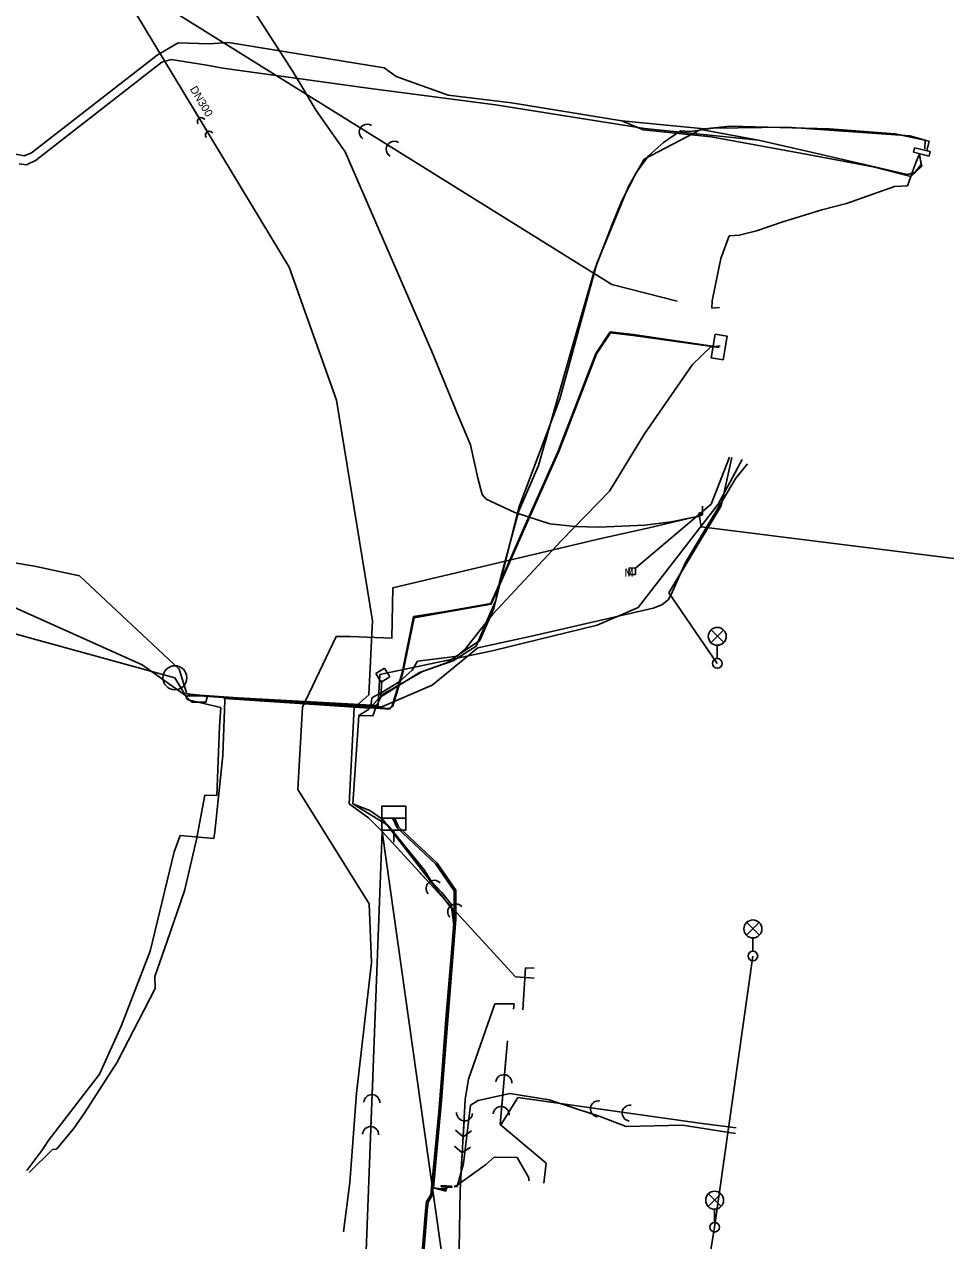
# Model space of a CAD drawing. Extents: x -880762 to -879575, y -1023083 to -1021277.
# Drawn here: x -880277.4 to -880162.3, y -1022636.5 to -1022484.5 of the extents above; entities that cross this region are included whole.
import ezdxf

# ---------------------------------------------------------------- set-up
doc = ezdxf.new("R2010")
doc.units = 0
for name, color, linetype in [('CETIN', 7, 'Continuous'), ('el_NN-dům_hrázného', 7, 'Continuous'), ('elektro skříň', 7, 'Continuous'), ('kanalizace trasa', 7, 'Continuous'), ('vedeni NN VN', 7, 'Continuous'), ('vedení sdělovací', 7, 'Continuous'), ('VODOVOD', 7, 'Continuous'), ('znaky inž sítí ostatní', 7, 'Continuous'), ('šoupe vodovod', 7, 'Continuous')]:
    doc.layers.add(name, color=color, linetype=linetype)

msp = doc.modelspace()

# ---------------------------------------------------------------- linework, layer by layer
at = {"layer": 'CETIN'}
for points in [[(-880193.98, -1022546.12), (-880196.64, -1022546.65), (-880199.92, -1022547.08), (-880205.66, -1022547.32), (-880208.59, -1022547.23), (-880211.79, -1022546.9), (-880216.17, -1022545.48), (-880219.74, -1022543.82), (-880220.26, -1022543.26), (-880220.79, -1022541.22), (-880221.68, -1022537.04), (-880223.2, -1022533.48), (-880226.53, -1022525.39), (-880237.36, -1022500.45), (-880240.99, -1022495.28), (-880243.91, -1022490.39), (-880249.48, -1022481.75)], [(-880192.72, -1022544.68), (-880192.72, -1022545.77)], [(-880192.72, -1022544.68), (-880192.72, -1022545.77)], [(-880193.98, -1022546.12), (-880199.21, -1022547.35), (-880205.76, -1022548.81), (-880231.39, -1022554.88), (-880231.51, -1022561.2), (-880236.72, -1022560.99), (-880238.48, -1022560.97), (-880242.7, -1022569.82), (-880243.26, -1022580.08), (-880234.35, -1022594.36), (-880234.08, -1022601.7), (-880235.96, -1022618.03), (-880236.79, -1022629.2), (-880237.56, -1022635.34)], [(-880192.72, -1022545.77), (-880193.29, -1022545.98), (-880193.98, -1022546.12)], [(-880193.19, -1022545.51), (-880192.72, -1022545.77)], [(-880193.19, -1022545.51), (-880192.87, -1022547.3), (-880158.34, -1022551.61), (-880115.31, -1022557.06), (-880085.69, -1022559.86), (-880050.13, -1022567.44), (-880017.98, -1022579.31), (-879984.34, -1022593.8), (-879953.77, -1022606.48), (-879894, -1022631.85), (-879832.89, -1022657.98), (-879784.6, -1022689.61), (-879745.83, -1022713), (-879719.83, -1022738.56), (-879689.51, -1022723.72), (-879660.2, -1022700.45), (-879600.68, -1022686.65), (-879574.8, -1022673.27)]]:
    msp.add_lwpolyline(points, dxfattribs=at)
at = {"layer": 'el_NN-dům_hrázného'}
msp.add_line((-880232.77, -1022566.49), (-880232.92, -1022568.52), dxfattribs=at)
for points in [[(-880164.93, -1022500.07), (-880164.9, -1022498.98), (-880166.82, -1022498.43), (-880182.19, -1022497.35), (-880191.37, -1022497.47), (-880194.24, -1022497.88), (-880195.47, -1022497.82), (-880197.57, -1022499.29), (-880199.48, -1022500.92), (-880200.97, -1022502.99), (-880202.82, -1022506.62), (-880203.99, -1022509.51), (-880205.18, -1022512.5), (-880206.22, -1022515.21), (-880209.03, -1022525), (-880213.2, -1022539.62), (-880215.71, -1022545.42), (-880218.02, -1022554.04), (-880218.53, -1022556.47), (-880219.6, -1022558.93), (-880221, -1022562.2), (-880223.86, -1022564.02), (-880228.07, -1022565.49), (-880232.92, -1022568.52), (-880233.53, -1022569.85), (-880233.9, -1022570.87), (-880235.67, -1022570.85), (-880236.38, -1022581.88), (-880231.99, -1022584.57), (-880227.47, -1022590.11), (-880226.59, -1022591.57), (-880225.28, -1022592.94), (-880224.1, -1022594.4), (-880223.77, -1022597.02), (-880224.77, -1022608.76), (-880225.72, -1022621.93), (-880226.31, -1022629.85), (-880224.76, -1022630.27)], [(-880224.76, -1022630.27), (-880224.73, -1022629.79)]]:
    msp.add_lwpolyline(points, dxfattribs=at)
at = {"layer": 'elektro skříň'}
for p, q in [((-880166.37, -1022500.49), (-880166.24, -1022499.93)), ((-880166.37, -1022500.49), (-880166.24, -1022499.93)), ((-880164.41, -1022500.96), (-880166.37, -1022500.49)), ((-880164.41, -1022500.96), (-880166.37, -1022500.49)), ((-880166.24, -1022499.93), (-880164.27, -1022500.4)), ((-880166.24, -1022499.93), (-880164.27, -1022500.4)), ((-880164.27, -1022500.4), (-880164.41, -1022500.96)), ((-880164.27, -1022500.4), (-880164.41, -1022500.96)), ((-880225.38, -1022629.72), (-880225.37, -1022629.57)), ((-880225.38, -1022629.72), (-880224.03, -1022629.82)), ((-880225.37, -1022629.57), (-880224.02, -1022629.66)), ((-880224.03, -1022629.82), (-880224.02, -1022629.66))]:
    msp.add_line(p, q, dxfattribs=at)
msp.add_lwpolyline([(-880190.14, -1022526.42), (-880189.65, -1022523.46), (-880191.13, -1022523.22), (-880191.62, -1022526.18)], close=True, dxfattribs=at)
at = {"layer": 'kanalizace trasa'}
for p, q in [((-880244.37, -1022514.84), (-880266.29, -1022478.48)), ((-880204.04, -1022517.02), (-880265.17, -1022478.94)), ((-880254.56, -1022497.94), (-880256.1, -1022495.38)), ((-880255.33, -1022496.66), (-880255.33, -1022496.66)), ((-880232.07, -1022499.58), (-880237.14, -1022496.38)), ((-880234.6, -1022497.98), (-880234.6, -1022497.98)), ((-880238.43, -1022531.47), (-880244.37, -1022514.84)), ((-880195.87, -1022519.1), (-880204.04, -1022517.02)), ((-880233.93, -1022559.01), (-880238.43, -1022531.47)), ((-880234.41, -1022568.27), (-880233.93, -1022559.01)), ((-880236.25, -1022569.9), (-880234.41, -1022568.27)), ((-880236.86, -1022581.87), (-880236.25, -1022569.9)), ((-880234.43, -1022583.65), (-880236.86, -1022581.87)), ((-880232.74, -1022585.34), (-880234.43, -1022583.65)), ((-880235.32, -1022653.05), (-880232.74, -1022585.34)), ((-880219.14, -1022681.54), (-880232.74, -1022585.34)), ((-880216.09, -1022603.48), (-880232.74, -1022585.34)), ((-880224.21, -1022594.64), (-880228.26, -1022590.21)), ((-880226.24, -1022592.43), (-880226.24, -1022592.43)), ((-880214.84, -1022602.37), (-880215.17, -1022607.61)), ((-880213.74, -1022602.41), (-880214.84, -1022602.37)), ((-880213.75, -1022603.66), (-880216.09, -1022603.48)), ((-880221.93, -1022616.28), (-880218.64, -1022606.87)), ((-880218.64, -1022606.87), (-880216.79, -1022606.86)), ((-880216.79, -1022606.86), (-880216.24, -1022606.87)), ((-880216.24, -1022606.87), (-880216.32, -1022607.55)), ((-880217.98, -1022621.94), (-880217.09, -1022611.47)), ((-880217.78, -1022619.69), (-880217.28, -1022613.72)), ((-880234.14, -1022622.19), (-880233.92, -1022616.2)), ((-880222.38, -1022618.8), (-880221.93, -1022616.28)), ((-880217.53, -1022616.71), (-880217.53, -1022616.71)), ((-880234.03, -1022619.2), (-880234.03, -1022619.2)), ((-880222.38, -1022618.8), (-880222.99, -1022630.16)), ((-880217.87, -1022621.92), (-880215.79, -1022618.55)), ((-880215.79, -1022618.55), (-880192.77, -1022621.81)), ((-880202.74, -1022620.38), (-880208.69, -1022619.58)), ((-880205.72, -1022619.98), (-880205.72, -1022619.98)), ((-880222.5, -1022621.49), (-880222.85, -1022627.48)), ((-880212.26, -1022626.76), (-880217.98, -1022621.94)), ((-880192.77, -1022621.81), (-880188.52, -1022622.34)), ((-880222.61, -1022623.49), (-880223.57, -1022622.63)), ((-880221.57, -1022622.75), (-880222.61, -1022623.49)), ((-880222.67, -1022624.49), (-880222.67, -1022624.49)), ((-880212.53, -1022629.26), (-880212.26, -1022626.76)), ((-880222.99, -1022630.16), (-880223.12, -1022637.53))]:
    msp.add_line(p, q, dxfattribs=at)
msp.add_lwpolyline([(-880221.69, -1022624.75), (-880222.73, -1022625.49), (-880223.68, -1022624.63)], dxfattribs=at)
for centre, radius, start, end in [((-880255.33, -1022496.66), 0.5, 31.0841, 211.0841), ((-880234.6, -1022497.98), 1, 57.7056, 237.7056), ((-880254.3, -1022498.37), 0.5, 31.0841, 211.0841), ((-880231.22, -1022500.12), 1, 57.7056, 237.7056), ((-880226.24, -1022592.43), 1, 42.3525, 222.3525), ((-880223.54, -1022595.38), 1, 42.3525, 222.3525), ((-880217.53, -1022616.71), 1, 355.2024, 175.2024), ((-880234.03, -1022619.2), 1, 357.8179, 177.8179), ((-880205.72, -1022619.98), 1, 82.324, 262.324), ((-880222.44, -1022620.49), 1, 176.6174, 356.6174), ((-880217.87, -1022620.69), 1, 355.2024, 175.2024), ((-880201.75, -1022620.51), 1, 82.324, 262.324), ((-880234.18, -1022623.19), 1, 357.8179, 177.8179)]:
    msp.add_arc(centre, radius, start, end, dxfattribs=at)
at = {"layer": 'vedeni NN VN'}
for p, q in [((-880275.89, -1022501.39), (-880260.26, -1022489.24)), ((-880260.26, -1022489.24), (-880259.11, -1022488.9)), ((-880259.11, -1022488.9), (-880254.62, -1022489.61)), ((-880254.62, -1022489.61), (-880252.63, -1022489.99)), ((-880252.63, -1022489.99), (-880240.24, -1022491.68)), ((-880240.24, -1022491.68), (-880234.54, -1022492.47)), ((-880234.54, -1022492.47), (-880218.57, -1022494.58)), ((-880218.57, -1022494.58), (-880199.97, -1022497.52)), ((-880200.01, -1022501.35), (-880192.93, -1022497.63)), ((-880199.97, -1022497.52), (-880185.7, -1022498.99)), ((-880192.93, -1022497.63), (-880185.7, -1022498.99)), ((-880185.7, -1022498.99), (-880179.13, -1022500.47)), ((-880179.13, -1022500.47), (-880167.12, -1022503.27)), ((-880278.09, -1022501.93), (-880277.15, -1022502.05)), ((-880277.15, -1022502.05), (-880275.86, -1022501.45)), ((-880275.86, -1022501.45), (-880275.89, -1022501.39)), ((-880201.96, -1022504.77), (-880200.01, -1022501.35)), ((-880166.06, -1022501.77), (-880167.12, -1022504.67)), ((-880166.21, -1022503.03), (-880165.39, -1022502.03)), ((-880165.59, -1022500.74), (-880166.06, -1022501.77)), ((-880165.39, -1022502.03), (-880165.59, -1022500.74)), ((-880167.12, -1022503.27), (-880166.21, -1022503.03)), ((-880205.91, -1022514.4), (-880201.96, -1022504.77)), ((-880168.75, -1022504.76), (-880174.72, -1022506.9)), ((-880167.12, -1022504.67), (-880168.75, -1022504.76)), ((-880177.82, -1022507.68), (-880182.67, -1022509.19)), ((-880174.72, -1022506.9), (-880177.82, -1022507.68)), ((-880182.67, -1022509.19), (-880185.97, -1022510.29)), ((-880189.39, -1022510.92), (-880190.43, -1022513.76)), ((-880188.14, -1022510.84), (-880189.39, -1022510.92)), ((-880185.97, -1022510.29), (-880188.14, -1022510.84)), ((-880210.54, -1022531.28), (-880205.91, -1022514.4)), ((-880190.43, -1022513.76), (-880191.52, -1022519.06)), ((-880191.52, -1022519.06), (-880191.56, -1022519.98)), ((-880191.56, -1022519.98), (-880190.6, -1022519.89)), ((-880204.25, -1022522.94), (-880206.03, -1022525.63)), ((-880205.96, -1022525.67), (-880204.21, -1022523.03)), ((-880201.38, -1022523.26), (-880204.25, -1022522.94)), ((-880204.21, -1022523.03), (-880201.38, -1022523.36)), ((-880201.38, -1022523.26), (-880190.63, -1022524.82)), ((-880190.62, -1022524.89), (-880201.38, -1022523.36)), ((-880191.71, -1022524.85), (-880193.97, -1022527.02)), ((-880191.71, -1022524.85), (-880190.52, -1022524.69)), ((-880210.75, -1022537.81), (-880206.03, -1022525.63)), ((-880205.96, -1022525.67), (-880210.66, -1022537.88)), ((-880193.97, -1022527.02), (-880199.95, -1022535.66)), ((-880215.67, -1022544.85), (-880210.54, -1022531.28)), ((-880199.95, -1022535.66), (-880204.34, -1022542.81)), ((-880215.02, -1022547.43), (-880210.75, -1022537.81)), ((-880210.66, -1022537.88), (-880214.94, -1022547.49)), ((-880190.37, -1022544.66), (-880189.05, -1022538.63)), ((-880188.54, -1022541.22), (-880187.09, -1022539.4)), ((-880194.83, -1022551.72), (-880188.54, -1022541.22)), ((-880204.34, -1022542.81), (-880210.33, -1022548.98)), ((-880196.91, -1022555.51), (-880190.37, -1022544.66)), ((-880276.15, -1022552.21), (-880312.94, -1022546.07)), ((-880218.77, -1022557.48), (-880215.67, -1022544.85)), ((-880215.02, -1022547.43), (-880219.16, -1022556.85)), ((-880219.1, -1022556.95), (-880214.94, -1022547.49)), ((-880210.33, -1022548.98), (-880218.94, -1022558.21)), ((-880270.54, -1022553.38), (-880276.15, -1022552.21)), ((-880196.64, -1022555.73), (-880194.83, -1022551.72)), ((-880258.09, -1022565.07), (-880270.54, -1022553.38)), ((-880224.83, -1022557.85), (-880219.16, -1022556.85)), ((-880197.8, -1022557.04), (-880197.02, -1022556.38)), ((-880197.02, -1022556.38), (-880196.64, -1022555.73)), ((-880190.87, -1022564.34), (-880196.91, -1022555.51)), ((-880279.11, -1022557.13), (-880262.71, -1022564.51)), ((-880228.81, -1022558.5), (-880224.83, -1022557.85)), ((-880224.79, -1022557.95), (-880228.75, -1022558.66)), ((-880219.1, -1022556.95), (-880224.79, -1022557.95)), ((-880220.53, -1022561.48), (-880218.77, -1022557.48)), ((-880218.94, -1022558.21), (-880220.39, -1022560.05)), ((-880214.08, -1022560.92), (-880198.88, -1022557.43)), ((-880198.88, -1022557.43), (-880197.8, -1022557.04)), ((-880230.25, -1022565.52), (-880228.81, -1022558.5)), ((-880228.75, -1022558.66), (-880230.17, -1022565.52)), ((-880224.7, -1022564.26), (-880220.53, -1022561.48)), ((-880220.39, -1022560.05), (-880222.33, -1022562.53)), ((-880220.8, -1022562.38), (-880214.08, -1022560.92)), ((-880226.48, -1022567.07), (-880220.8, -1022562.38)), ((-880222.33, -1022562.53), (-880223.38, -1022563.44)), ((-880262.71, -1022564.51), (-880257.2, -1022568.44)), ((-880228.33, -1022564.07), (-880229, -1022565.17)), ((-880224.6, -1022563.59), (-880228.33, -1022564.07)), ((-880227.69, -1022565.33), (-880224.7, -1022564.26)), ((-880223.38, -1022563.44), (-880224.6, -1022563.59)), ((-880257.13, -1022568.16), (-880258.09, -1022565.07)), ((-880227.69, -1022565.33), (-880232.71, -1022568.22)), ((-880230.25, -1022565.52), (-880231.47, -1022569.65)), ((-880231.42, -1022569.7), (-880230.17, -1022565.52)), ((-880229, -1022565.17), (-880230.61, -1022566.66)), ((-880232.92, -1022568.52), (-880232.77, -1022566.49)), ((-880232.79, -1022569.78), (-880226.48, -1022567.07)), ((-880230.61, -1022566.66), (-880232.65, -1022567.87)), ((-880257.2, -1022568.51), (-880256.81, -1022568.26)), ((-880257.2, -1022568.44), (-880255.68, -1022568.38)), ((-880257.17, -1022568.72), (-880257.2, -1022568.51)), ((-880256.97, -1022568.89), (-880257.17, -1022568.72)), ((-880255.53, -1022568.29), (-880257.13, -1022568.16)), ((-880252.89, -1022569.85), (-880256.97, -1022568.89)), ((-880255.54, -1022568.37), (-880256.81, -1022568.26)), ((-880255.68, -1022568.38), (-880232.79, -1022569.78)), ((-880255.54, -1022568.37), (-880234.15, -1022569.91)), ((-880234.13, -1022569.8), (-880255.53, -1022568.29)), ((-880252.65, -1022575.84), (-880252.37, -1022568.99)), ((-880234.96, -1022569.9), (-880252.44, -1022568.73)), ((-880252.44, -1022568.73), (-880252.37, -1022568.99)), ((-880234.44, -1022570.1), (-880232.71, -1022568.22)), ((-880234.03, -1022568.65), (-880234.13, -1022569.4)), ((-880232.65, -1022567.87), (-880234.03, -1022568.65)), ((-880233.53, -1022569.85), (-880232.92, -1022568.52)), ((-880252.89, -1022569.85), (-880253.04, -1022572.22)), ((-880235.67, -1022570.85), (-880234.44, -1022570.1)), ((-880234.23, -1022569.92), (-880234.96, -1022569.9)), ((-880234.13, -1022569.4), (-880234.23, -1022569.92)), ((-880234.15, -1022569.91), (-880231.81, -1022570.06)), ((-880231.83, -1022569.98), (-880234.13, -1022569.8)), ((-880233.9, -1022570.87), (-880233.53, -1022569.85)), ((-880231.83, -1022569.98), (-880231.47, -1022569.65)), ((-880231.81, -1022570.06), (-880231.42, -1022569.7)), ((-880236.38, -1022581.88), (-880235.67, -1022570.85)), ((-880236.38, -1022581.88), (-880235.67, -1022570.85)), ((-880235.67, -1022570.85), (-880233.9, -1022570.87)), ((-880253.04, -1022572.22), (-880253.41, -1022580.84)), ((-880253.64, -1022585.36), (-880252.65, -1022575.84)), ((-880254.9, -1022580.78), (-880255.94, -1022586.33)), ((-880253.41, -1022580.84), (-880254.9, -1022580.78)), ((-880231.99, -1022584.57), (-880236.38, -1022581.88)), ((-880234.29, -1022582.73), (-880236.38, -1022581.88)), ((-880234.29, -1022582.73), (-880232.67, -1022583.85)), ((-880232.67, -1022583.85), (-880223.85, -1022595.21)), ((-880253.77, -1022586.23), (-880253.64, -1022585.36)), ((-880227.47, -1022590.11), (-880231.99, -1022584.57)), ((-880258.7, -1022587.87), (-880257.98, -1022585.82)), ((-880257.98, -1022585.82), (-880253.77, -1022586.23)), ((-880255.94, -1022586.33), (-880257.43, -1022592.75)), ((-880261.71, -1022600.28), (-880258.7, -1022587.87)), ((-880226.59, -1022591.57), (-880227.47, -1022590.11)), ((-880225.28, -1022592.94), (-880226.59, -1022591.57)), ((-880257.43, -1022592.75), (-880259.59, -1022599.05)), ((-880224.1, -1022594.4), (-880225.28, -1022592.94)), ((-880223.77, -1022597.02), (-880224.1, -1022594.4)), ((-880223.68, -1022595.8), (-880224.27, -1022605.05)), ((-880223.85, -1022595.21), (-880223.68, -1022595.8)), ((-880224.77, -1022608.76), (-880223.77, -1022597.02)), ((-880259.59, -1022599.05), (-880261.13, -1022603.44)), ((-880265.35, -1022609.67), (-880261.71, -1022600.28)), ((-880186.42, -1022600.89), (-880191.2, -1022634.77)), ((-880261.13, -1022603.44), (-880261.1, -1022604.96)), ((-880261.1, -1022604.96), (-880265.84, -1022614.15)), ((-880224.27, -1022605.05), (-880225.27, -1022618.45)), ((-880268.05, -1022615.63), (-880265.35, -1022609.67)), ((-880225.72, -1022621.93), (-880224.77, -1022608.76)), ((-880265.84, -1022614.15), (-880269.87, -1022620.45)), ((-880274.46, -1022623.96), (-880268.05, -1022615.63)), ((-880226.31, -1022629.85), (-880225.27, -1022618.45)), ((-880221.71, -1022619.53), (-880220.73, -1022618.96)), ((-880220.73, -1022618.96), (-880216.77, -1022618.08)), ((-880216.77, -1022618.08), (-880211.87, -1022618.85)), ((-880211.87, -1022618.85), (-880208.34, -1022620.01)), ((-880269.87, -1022620.45), (-880271.3, -1022622.46)), ((-880222.56, -1022626.79), (-880221.71, -1022619.53)), ((-880208.34, -1022620.01), (-880205.62, -1022620.89)), ((-880226.31, -1022629.85), (-880225.72, -1022621.93)), ((-880205.62, -1022620.89), (-880202.24, -1022622.17)), ((-880202.24, -1022622.17), (-880195.22, -1022622.03)), ((-880195.22, -1022622.03), (-880188.59, -1022623.06)), ((-880271.3, -1022622.46), (-880273.44, -1022625.02)), ((-880277.12, -1022627.67), (-880275.11, -1022625.02)), ((-880273.94, -1022625.05), (-880276.82, -1022627.95)), ((-880275.11, -1022625.02), (-880274.46, -1022623.96)), ((-880273.44, -1022625.02), (-880273.94, -1022625.05)), ((-880223.36, -1022629.68), (-880222.56, -1022626.79)), ((-880218.76, -1022626.01), (-880219.81, -1022626.97)), ((-880215.85, -1022626.08), (-880218.76, -1022626.01)), ((-880214.41, -1022628.59), (-880215.85, -1022626.08)), ((-880223.25, -1022629.45), (-880219.81, -1022626.97)), ((-880219.81, -1022626.97), (-880223.25, -1022629.45)), ((-880226.31, -1022629.85), (-880224.78, -1022630.05)), ((-880225.61, -1022629.98), (-880226.31, -1022629.85)), ((-880224.78, -1022630.05), (-880224.73, -1022629.79)), ((-880224.65, -1022629.96), (-880224.63, -1022629.78)), ((-880223.72, -1022629.74), (-880223.25, -1022629.45)), ((-880223.36, -1022629.68), (-880223.72, -1022629.74)), ((-880214.41, -1022628.59), (-880214.42, -1022628.96)), ((-880225.61, -1022629.98), (-880224.65, -1022629.96)), ((-880225.61, -1022629.98), (-880224.65, -1022629.96)), ((-880191.2, -1022634.77), (-880194.67, -1022655.39))]:
    msp.add_line(p, q, dxfattribs=at)
at = {"layer": 'vedení sdělovací'}
for p, q in [((-880258.22, -1022486.8), (-880260.83, -1022488.38)), ((-880254.33, -1022486.93), (-880258.22, -1022486.8)), ((-880251.95, -1022486.77), (-880254.33, -1022486.93)), ((-880232.5, -1022489.93), (-880251.95, -1022486.77)), ((-880260.83, -1022488.38), (-880276.53, -1022500.54)), ((-880231, -1022491.02), (-880232.5, -1022489.93)), ((-880224.47, -1022493.35), (-880231, -1022491.02)), ((-880216.56, -1022494.32), (-880224.47, -1022493.35)), ((-880202.8, -1022496.57), (-880216.56, -1022494.32)), ((-880200.13, -1022497.67), (-880202.8, -1022496.57)), ((-880202.8, -1022496.57), (-880192.48, -1022497.58)), ((-880191.65, -1022498.57), (-880200.13, -1022497.67)), ((-880192.48, -1022497.58), (-880189.28, -1022497.24)), ((-880189.28, -1022497.24), (-880176.84, -1022497.56)), ((-880176.84, -1022497.56), (-880168.63, -1022498.19)), ((-880179.34, -1022500.83), (-880191.65, -1022498.57)), ((-880168.63, -1022498.19), (-880164.39, -1022499.09)), ((-880164.39, -1022499.09), (-880164.68, -1022500.3)), ((-880277.44, -1022500.92), (-880278.76, -1022500.68)), ((-880276.53, -1022500.54), (-880277.44, -1022500.92)), ((-880165.31, -1022502.23), (-880165.63, -1022500.7)), ((-880179.34, -1022500.83), (-880171.39, -1022502.29)), ((-880166.69, -1022503.52), (-880165.31, -1022502.23)), ((-880171.39, -1022502.29), (-880166.69, -1022503.52)), ((-880191.65, -1022544.45), (-880189.33, -1022538.58)), ((-880201.09, -1022552.43), (-880191.65, -1022544.45))]:
    msp.add_line(p, q, dxfattribs=at)
at = {"layer": 'VODOVOD'}
for p, q in [((-880428.02, -1022519.5), (-880258.63, -1022566.13)), ((-880187.78, -1022538.85), (-880190.74, -1022544.45)), ((-880190.74, -1022544.45), (-880200.75, -1022557.34)), ((-880200.75, -1022557.34), (-880205.86, -1022559.57)), ((-880205.86, -1022559.57), (-880219.01, -1022562.79)), ((-880219.01, -1022562.79), (-880233.04, -1022565.72)), ((-880233.23, -1022569.59), (-880233.04, -1022565.72)), ((-880258.63, -1022566.13), (-880257.11, -1022568.69)), ((-880257.11, -1022568.69), (-880256.46, -1022569.2)), ((-880254.78, -1022569.2), (-880254.56, -1022568.42)), ((-880254.56, -1022568.42), (-880233.23, -1022569.59)), ((-880256.46, -1022569.2), (-880254.78, -1022569.2)), ((-880230.87, -1022584.86), (-880231.39, -1022583.72)), ((-880231.21, -1022583.64), (-880230.7, -1022584.74)), ((-880230.87, -1022584.86), (-880226.03, -1022589.42)), ((-880225.88, -1022589.29), (-880230.7, -1022584.74)), ((-880226.03, -1022589.42), (-880223.73, -1022592.74)), ((-880223.53, -1022592.68), (-880225.88, -1022589.29)), ((-880223.73, -1022592.74), (-880223.73, -1022596.27)), ((-880223.53, -1022596.28), (-880223.53, -1022592.68)), ((-880223.73, -1022596.27), (-880225.66, -1022620.37)), ((-880225.46, -1022620.39), (-880223.53, -1022596.28)), ((-880225.66, -1022620.37), (-880226.66, -1022630.72)), ((-880226.47, -1022630.79), (-880225.46, -1022620.39)), ((-880226.66, -1022630.72), (-880227.18, -1022631.56)), ((-880226.99, -1022631.63), (-880226.47, -1022630.79)), ((-880227.32, -1022632.78), (-880228.28, -1022644.52)), ((-880228.08, -1022644.54), (-880227.11, -1022632.7)), ((-880227.18, -1022631.56), (-880227.32, -1022632.78)), ((-880227.11, -1022632.7), (-880226.99, -1022631.63))]:
    msp.add_line(p, q, dxfattribs=at)
at = {"layer": 'znaky inž sítí ostatní'}
for p, q in [((-880201.9, -1022553.22), (-880201.89, -1022552.42)), ((-880201.1, -1022553.23), (-880201.9, -1022553.22)), ((-880201.89, -1022552.42), (-880201.09, -1022552.43)), ((-880201.09, -1022552.43), (-880201.1, -1022553.23)), ((-880191.66, -1022561.75), (-880190.08, -1022560.17)), ((-880190.05, -1022561.74), (-880191.64, -1022560.16)), ((-880190.87, -1022563.74), (-880190.87, -1022562.09)), ((-880232.44, -1022564.95), (-880233.52, -1022565.62)), ((-880233.52, -1022565.62), (-880232.44, -1022564.95)), ((-880233.52, -1022565.62), (-880232.85, -1022566.7)), ((-880232.85, -1022566.7), (-880233.52, -1022565.62)), ((-880232.85, -1022566.7), (-880231.77, -1022566.03)), ((-880231.77, -1022566.03), (-880232.85, -1022566.7)), ((-880231.77, -1022566.03), (-880232.44, -1022564.95)), ((-880232.44, -1022564.95), (-880231.77, -1022566.03)), ((-880187.21, -1022598.3), (-880185.63, -1022596.72)), ((-880185.6, -1022598.29), (-880187.19, -1022596.71)), ((-880186.42, -1022600.29), (-880186.42, -1022598.64)), ((-880191.99, -1022632.18), (-880190.41, -1022630.6)), ((-880190.38, -1022632.18), (-880191.97, -1022630.59)), ((-880191.2, -1022634.17), (-880191.2, -1022632.52))]:
    msp.add_line(p, q, dxfattribs=at)
for centre, radius in [((-880190.87, -1022560.96), 1.12), ((-880190.87, -1022564.34), 0.6), ((-880186.42, -1022597.51), 1.12), ((-880186.42, -1022600.89), 0.6), ((-880191.2, -1022631.4), 1.12), ((-880191.2, -1022634.77), 0.6)]:
    msp.add_circle(centre, radius, dxfattribs=at)
at = {"layer": 'šoupe vodovod'}
msp.add_line((-880231.29, -1022586.69), (-880231.29, -1022585.19), dxfattribs=at)
msp.add_lwpolyline([(-880232.79, -1022583.69), (-880232.79, -1022582.19), (-880229.79, -1022582.19), (-880229.79, -1022583.69)], dxfattribs=at)
msp.add_lwpolyline([(-880232.79, -1022585.19), (-880229.79, -1022585.19), (-880229.79, -1022583.69), (-880232.79, -1022583.69)], close=True, dxfattribs=at)
msp.add_circle((-880258.63, -1022566.13), 1.5, dxfattribs=at)

# ---------------------------------------------------------------- texts
at = {"layer": 'kanalizace trasa'}
msp.add_text('DN300', height=1, rotation=300.7533, dxfattribs=at).set_placement((-880256.8, -1022492.59))
at = {"layer": 'znaky inž sítí ostatní'}
msp.add_text('M', height=1, rotation=360, dxfattribs=at).set_placement((-880202.45, -1022553.49))

doc.saveas('drawing.dxf')
